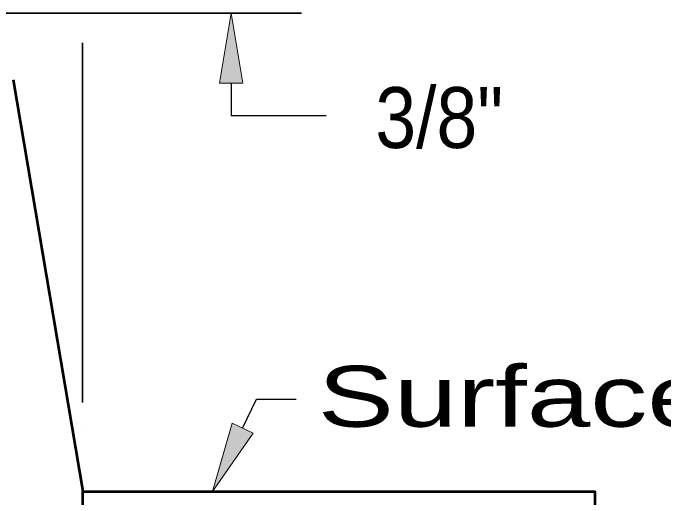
# Model space of a CAD drawing. Extents: x 36.6 to 71.9, y 0.8 to 22.8.
# Drawn here: x 56.961 to 58.631, y 19.019 to 20.263 of the extents above; entities that cross this region are included whole.
import ezdxf

# ---------------------------------------------------------------- set-up
doc = ezdxf.new("R2010")
doc.units = 0
doc.header["$LTSCALE"] = 0.062
for name, color, linetype, lineweight in [('1', 7, 'Continuous', 13), ('3', 7, 'Continuous', 25), ('8', 7, 'Continuous', 13)]:
    doc.layers.add(name, color=color, linetype=linetype, lineweight=lineweight)

msp = doc.modelspace()

# ---------------------------------------------------------------- hatches: boundary and pattern name
at = {"layer": '1'}
msp.add_hatch(color=256, dxfattribs=at).paths.add_polyline_path([(57.5505, 20.08308), (57.49042, 20.08308), (57.5205, 20.26308), (57.5205, 20.26308)])
at = {"layer": '3'}
msp.add_hatch(color=256, dxfattribs=at).paths.add_polyline_path([(57.57667, 19.185), (57.52258, 19.21083), (57.472, 19.03558), (57.472, 19.03558)])

# ---------------------------------------------------------------- linework, layer by layer
at = {"layer": '1', "lineweight": 35}
for p, q in [((56.92408, 20.26308), (57.7005, 20.26308)), ((57.139, 19.26433), (57.139, 20.18675))]:
    msp.add_line(p, q, dxfattribs=at)
at = {"layer": '1', "lineweight": 53}
msp.add_line((56.96058, 20.09158), (57.13942, 19.03558), dxfattribs=at)
at = {"layer": '1', "lineweight": 25}
for p in [(57.5205, 20.08308), (57.76417, 19.9995)]:
    msp.add_line(p, (57.5205, 19.9995), dxfattribs=at)
at = {"layer": '1'}
msp.add_lwpolyline([(57.5505, 20.08308), (57.49042, 20.08308), (57.5205, 20.26308), (57.5205, 20.26308)], close=True, dxfattribs=at)
at = {"layer": '1', "lineweight": 53}
for points in [[(55.87025, 16.68067), (57.13942, 16.68067), (57.13942, 19.03558)], [(57.13942, 19.03558), (58.45283, 19.03558), (58.45283, 18.681)]]:
    msp.add_lwpolyline(points, dxfattribs=at)
at = {"layer": '3'}
msp.add_lwpolyline([(57.54967, 19.19792), (57.58558, 19.273), (57.687, 19.273)], dxfattribs=at)
at = {"layer": '3', "lineweight": 13}
msp.add_lwpolyline([(57.57667, 19.185), (57.52258, 19.21083), (57.472, 19.03558), (57.472, 19.03558)], close=True, dxfattribs=at)
at = {"layer": '8'}
for p, q in [((57.5205, 20.26308), (57.52058, 20.26308)), ((57.139, 19.20183), (57.13908, 19.20183))]:
    msp.add_line(p, q, dxfattribs=at)

# ---------------------------------------------------------------- texts
at = {"layer": '3'}
for s, width, p in [('3/8"', 0.9, (57.89017, 19.91683)), ('Surface', 1.4, (57.7425, 19.20183))]:
    msp.add_text(s, height=0.1562, dxfattribs=dict(at, width=width)).set_placement(p)

doc.saveas('drawing.dxf')
